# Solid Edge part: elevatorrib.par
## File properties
Author: harmonj5
Template: ansi part.par
Last saved by: harmonj5
Revision: 7
Application: Solid Edge
Accuracy: 0.990
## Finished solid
Body 1: solid body, 24 faces, 66 edges, 44 vertices.
  Faces by surface: plane 18, swept 6
  Edges by curve: line 54, spline 12
Bounding box of the edges (mm; curved faces can reach further): 98.425 x 3.175 x 13.985, from (-46.8863, -3.175, 35.9583) to (51.5387, 0, 49.9436).
Planar faces by outward normal: +x 3, +y 1, +z 2, -x 3, -y 1, -z 1, oblique 7
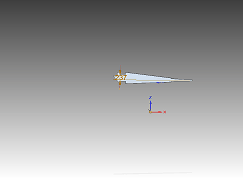
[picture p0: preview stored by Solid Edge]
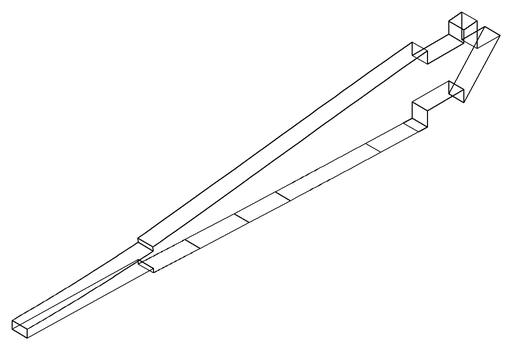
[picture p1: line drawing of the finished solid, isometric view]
